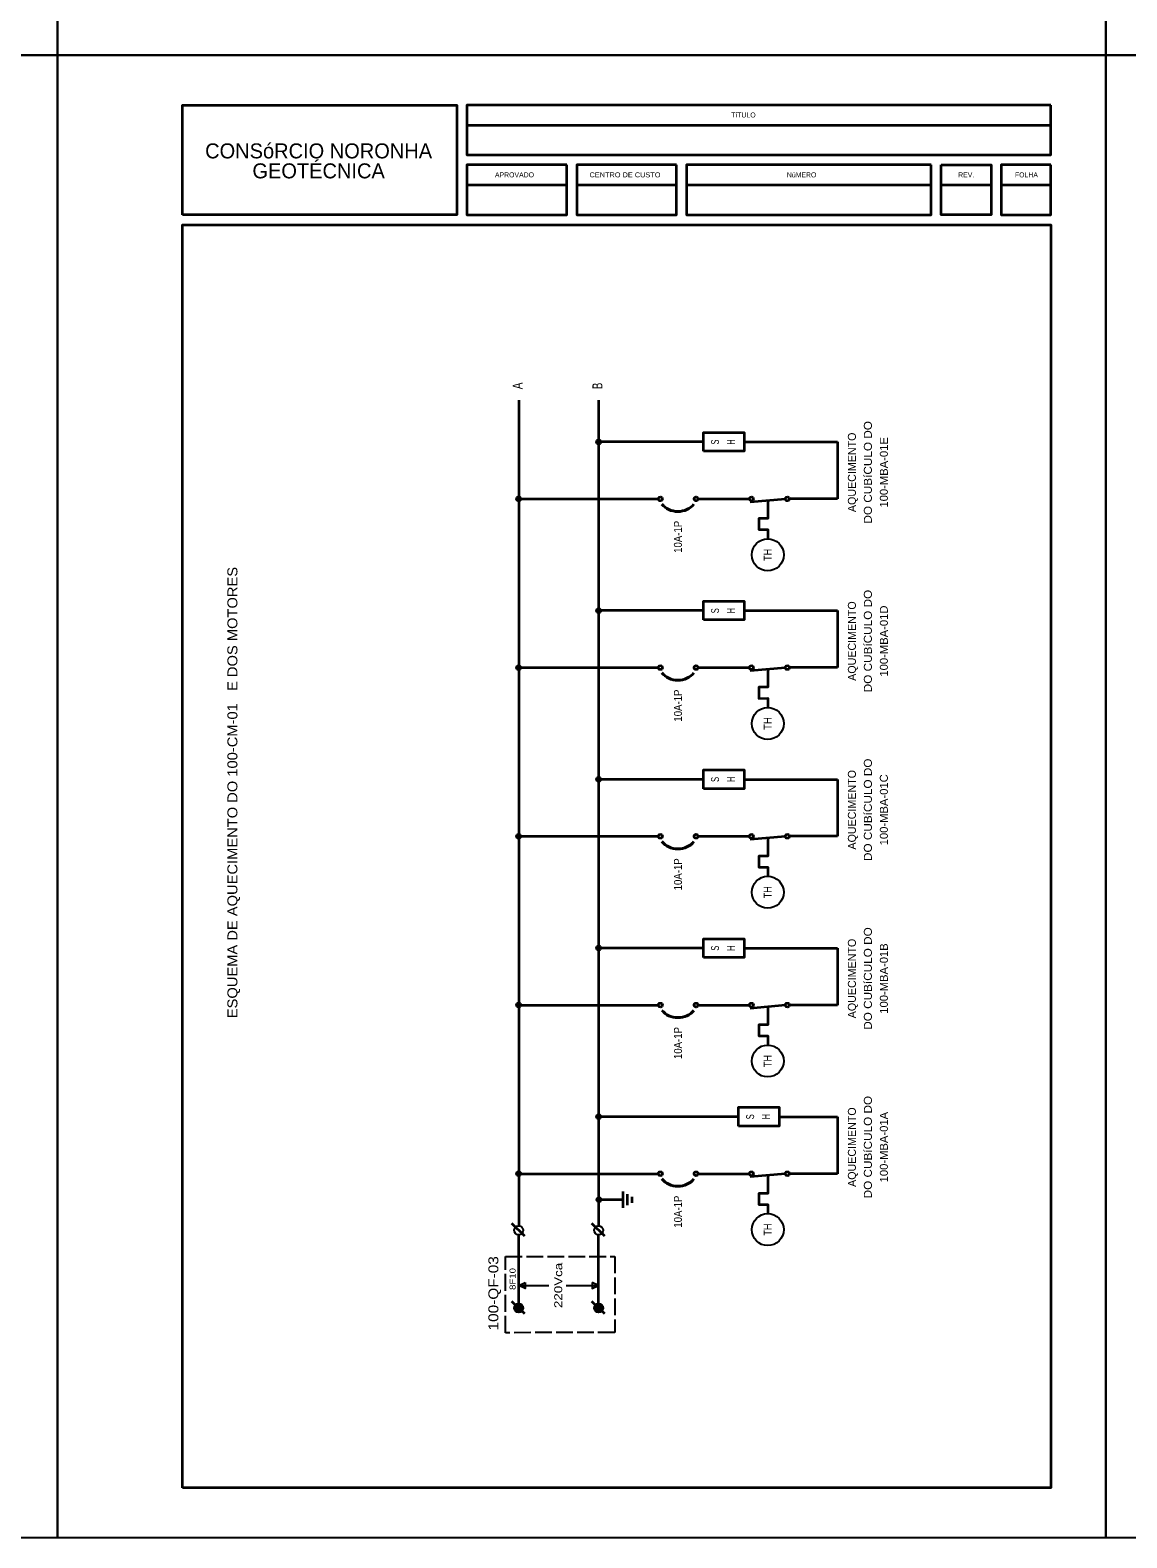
# Model space of a CAD drawing. Extents: x -4160 to -2690, y -474 to 714.
# Drawn here: x -3535.3 to -3315.6, y -473.5 to -171.5 of the extents above; entities that cross this region are included whole.
import ezdxf
from ezdxf.enums import TextEntityAlignment as Align

# ---------------------------------------------------------------- set-up
doc = ezdxf.new("R2010")
doc.units = 0
doc.header["$LTSCALE"] = 0.56
doc.linetypes.add('LONG_DASHED', pattern=[7.5, 6, -1.5])
doc.layers.add('2', color=7, linetype='Continuous', lineweight=25)
doc.layers.add('5', color=7, linetype='Continuous', lineweight=35)

msp = doc.modelspace()

# ---------------------------------------------------------------- hatches: boundary and pattern name
at = {"layer": '2'}
for points in [[(-3421.3942, -253.5808, 1), (-3421.3942, -254.4059, 1)], [(-3437.3942, -264.9938, 1), (-3437.3942, -265.819, 1)], [(-3421.3942, -287.3783, 1), (-3421.3942, -288.2035, 1)], [(-3437.3942, -298.7913, 1), (-3437.3942, -299.6165, 1)], [(-3421.3942, -321.1758, 1), (-3421.3942, -322.001, 1)], [(-3437.3942, -332.5889, 1), (-3437.3942, -333.414, 1)], [(-3421.3942, -354.9733, 1), (-3421.3942, -355.7985, 1)], [(-3437.3942, -366.3864, 1), (-3437.3942, -367.2115, 1)], [(-3421.3942, -388.7485, 1), (-3421.3942, -389.5736, 1)], [(-3437.3942, -400.1615, 1), (-3437.3942, -400.9867, 1)], [(-3421.3223, -405.3516, 1), (-3421.3223, -406.1767, 1)], [(-3437.3942, -428.3871, 1), (-3437.3942, -426.5889, 1)], [(-3421.3942, -428.3871, 1), (-3421.3942, -426.5889, 1)]]:
    msp.add_hatch(color=256, dxfattribs=at).paths.add_polyline_path(points)

# ---------------------------------------------------------------- linework, layer by layer
at = {"layer": '2', "lineweight": 35}
for p, q in [((-3437.3942, -245.6097), (-3437.3942, -411.0029)), ((-3421.3942, -245.6097), (-3421.3942, -411.0029)), ((-3400.4033, -253.9934), (-3421.3942, -253.9934)), ((-3392.219, -253.9934), (-3373.5488, -253.9934)), ((-3373.5488, -253.9934), (-3373.5488, -265.4064)), ((-3437.3942, -265.4064), (-3409.4143, -265.4064)), ((-3401.4522, -265.4064), (-3391.17, -265.4064)), ((-3383.9686, -265.4417), (-3391.0324, -266.0671)), ((-3373.5488, -265.4064), (-3383.1702, -265.4064)), ((-3400.4033, -287.7909), (-3421.3942, -287.7909)), ((-3392.219, -287.7909), (-3373.5488, -287.7909)), ((-3373.5488, -287.7909), (-3373.5488, -299.2039)), ((-3437.3942, -299.2039), (-3409.4143, -299.2039)), ((-3401.4522, -299.2039), (-3391.17, -299.2039)), ((-3383.9686, -299.2392), (-3391.0324, -299.8646)), ((-3373.5488, -299.2039), (-3383.1702, -299.2039)), ((-3400.4033, -321.5884), (-3421.3942, -321.5884)), ((-3392.219, -321.5884), (-3373.5488, -321.5884)), ((-3373.5488, -321.5884), (-3373.5488, -333.0014)), ((-3437.3942, -333.0014), (-3409.4143, -333.0014)), ((-3401.4522, -333.0014), (-3391.17, -333.0014)), ((-3383.9686, -333.0367), (-3391.0324, -333.6622)), ((-3373.5488, -333.0014), (-3383.1702, -333.0014)), ((-3400.4033, -355.3859), (-3421.3942, -355.3859)), ((-3392.219, -355.3859), (-3373.5488, -355.3859)), ((-3373.5488, -355.3859), (-3373.5488, -366.799)), ((-3437.3942, -366.799), (-3409.4143, -366.799)), ((-3401.4522, -366.799), (-3391.17, -366.799)), ((-3383.9686, -366.8342), (-3391.0324, -367.4597)), ((-3373.5488, -366.799), (-3383.1702, -366.799)), ((-3393.371, -389.161), (-3421.3942, -389.161)), ((-3385.1867, -389.161), (-3373.5488, -389.161)), ((-3373.5488, -389.161), (-3373.5488, -400.5741)), ((-3437.3942, -400.5741), (-3409.4143, -400.5741)), ((-3401.4522, -400.5741), (-3391.17, -400.5741)), ((-3383.9686, -400.6094), (-3391.0324, -401.2348)), ((-3373.5488, -400.5741), (-3383.1702, -400.5741)), ((-3416.4845, -407.4128), (-3416.4845, -404.1154)), ((-3415.6035, -406.9088), (-3415.6035, -404.6796)), ((-3421.3223, -405.7642), (-3416.4845, -405.7642)), ((-3414.6761, -406.3979), (-3414.6761, -405.1904)), ((-3438.8271, -410.5106), (-3436.2302, -413.0283)), ((-3422.8271, -410.5106), (-3420.2302, -413.0283)), ((-3437.3942, -426.5889), (-3437.3942, -412.8011)), ((-3421.3942, -426.5889), (-3421.3942, -412.8011)), ((-3438.8271, -426.0966), (-3436.2302, -428.6143)), ((-3422.8271, -426.0966), (-3420.2302, -428.6143))]:
    msp.add_line(p, q, dxfattribs=at)
at = {"layer": '2'}
for p, q in [((-3437.3942, -422.9972), (-3431.3293, -422.9972)), ((-3427.8636, -422.9972), (-3421.3942, -422.9972))]:
    msp.add_line(p, q, dxfattribs=at)
at = {"layer": '2', "lineweight": 35}
for points in [[(-3400.4032, -255.8692), (-3400.4032, -252.1176), (-3392.219, -252.1176), (-3392.219, -255.8692)], [(-3400.4032, -289.6667), (-3400.4032, -285.9151), (-3392.219, -285.9151), (-3392.219, -289.6667)], [(-3400.4032, -323.4642), (-3400.4032, -319.7126), (-3392.219, -319.7126), (-3392.219, -323.4642)], [(-3400.4032, -357.2618), (-3400.4032, -353.5102), (-3392.219, -353.5102), (-3392.219, -357.2618)], [(-3393.3709, -391.0369), (-3393.3709, -387.2853), (-3385.1867, -387.2853), (-3385.1867, -391.0369)]]:
    msp.add_lwpolyline(points, close=True, dxfattribs=at)
for points in [[(-3387.5005, -265.7544), (-3387.5005, -269.3482), (-3389.3112, -269.3482), (-3389.3112, -271.5726), (-3387.5005, -271.5612), (-3387.5005, -273.4161)], [(-3387.5005, -299.5519), (-3387.5005, -303.1457), (-3389.3112, -303.1457), (-3389.3112, -305.3702), (-3387.5005, -305.3587), (-3387.5005, -307.2136)], [(-3387.5005, -333.3494), (-3387.5005, -336.9432), (-3389.3112, -336.9432), (-3389.3112, -339.1677), (-3387.5005, -339.1562), (-3387.5005, -341.0111)], [(-3387.5005, -367.147), (-3387.5005, -370.7407), (-3389.3112, -370.7407), (-3389.3112, -372.9652), (-3387.5005, -372.9538), (-3387.5005, -374.8086)], [(-3387.5005, -400.9221), (-3387.5005, -404.5158), (-3389.3112, -404.5158), (-3389.3112, -406.7403), (-3387.5005, -406.7289), (-3387.5005, -408.5838)]]:
    msp.add_lwpolyline(points, dxfattribs=at)
at = {"layer": '2', "linetype": 'LONG_DASHED'}
msp.add_lwpolyline([(-3440.0501, -432.4233), (-3440.0501, -417.1922), (-3418.1535, -417.1701), (-3418.1535, -432.4012)], close=True, dxfattribs=at)
at = {"layer": '2'}
for points in [[(-3436.1214, -422.3926), (-3436.1214, -423.6019), (-3437.3942, -422.9972)], [(-3422.667, -422.3926), (-3422.667, -423.6019), (-3421.3942, -422.9972)]]:
    msp.add_lwpolyline(points, close=True, dxfattribs=at)
at = {"layer": '2', "lineweight": 35}
for centre, radius in [((-3421.3942, -253.9934), 0.4126), ((-3437.3942, -265.4064), 0.4126), ((-3409.0143, -265.4064), 0.4), ((-3401.8522, -265.4064), 0.4), ((-3390.77, -265.4064), 0.4), ((-3383.5701, -265.4064), 0.4), ((-3421.3942, -287.7909), 0.4126), ((-3437.3942, -299.2039), 0.4126), ((-3409.0143, -299.2039), 0.4), ((-3401.8522, -299.204), 0.4), ((-3390.77, -299.2039), 0.4), ((-3383.5701, -299.2039), 0.4), ((-3421.3942, -321.5884), 0.4126), ((-3437.3942, -333.0014), 0.4126), ((-3409.0143, -333.0014), 0.4), ((-3401.8522, -333.0015), 0.4), ((-3390.77, -333.0014), 0.4), ((-3383.5701, -333.0014), 0.4), ((-3421.3942, -355.3859), 0.4126), ((-3437.3942, -366.799), 0.4126), ((-3409.0143, -366.7989), 0.4), ((-3401.8522, -366.799), 0.4), ((-3390.77, -366.7989), 0.4), ((-3383.5701, -366.7989), 0.4), ((-3421.3942, -389.161), 0.4126), ((-3437.3942, -400.5741), 0.4126), ((-3409.0143, -400.574), 0.4), ((-3401.8522, -400.5741), 0.4), ((-3390.77, -400.574), 0.4), ((-3383.5701, -400.574), 0.4), ((-3421.3223, -405.7642), 0.4126)]:
    msp.add_circle(centre, radius, dxfattribs=at)
at = {"layer": '2'}
for centre, radius in [((-3387.5005, -276.6144), 3.1984), ((-3387.5005, -310.412), 3.1984), ((-3387.5005, -344.2095), 3.1984), ((-3387.5005, -378.007), 3.1984), ((-3387.5005, -411.7821), 3.1984), ((-3437.3942, -411.902), 0.8991), ((-3421.3942, -411.902), 0.8991), ((-3437.3942, -427.488), 0.8991), ((-3421.3942, -427.488), 0.8991)]:
    msp.add_circle(centre, radius, dxfattribs=at)
at = {"layer": '2', "lineweight": 40}
for centre in [(-3405.4993, -264.6915), (-3405.4993, -298.489), (-3405.4993, -332.2865), (-3405.4993, -366.084), (-3405.4993, -399.8591)]:
    msp.add_ellipse(centre, major_axis=(-3.8115, 0), ratio=0.85, start_param=0.57974073, end_param=2.56185197, dxfattribs=at)
at = {"layer": '5', "lineweight": 25}
for p, q in [((-3529.7642, -176.52), (-3529.7642, 120.48)), ((-3529.7642, 120.48), (-3529.7642, -176.52)), ((-3529.7642, -473.52), (-3529.7642, -176.52)), ((-3529.7642, -473.5197), (-3529.7642, -176.52)), ((-3529.7642, -473.5197), (-3739.764, -473.5197)), ((-3319.7642, -473.52), (-3529.7642, -473.52))]:
    msp.add_line(p, q, dxfattribs=at)
at = {"layer": '5'}
for p, q in [((-3447.7642, -190.52), (-3330.7642, -190.52)), ((-3447.7642, -202.52), (-3427.7642, -202.52)), ((-3425.7642, -202.52), (-3405.7642, -202.52)), ((-3403.7642, -202.52), (-3354.7642, -202.52)), ((-3352.7642, -202.52), (-3342.7642, -202.52)), ((-3340.7642, -202.52), (-3330.7642, -202.52))]:
    msp.add_line(p, q, dxfattribs=at)
at = {"layer": '5', "lineweight": 25}
for points in [[(-3319.7642, -176.52), (-3529.7642, -176.52), (-3529.7642, 120.48), (-3319.7642, 120.48)], [(-3109.7642, -176.52), (-3319.7642, -176.52), (-3319.7642, 120.48), (-3109.7642, 120.48)], [(-3109.7642, -473.52), (-3319.7642, -473.52), (-3319.7642, -176.52), (-3109.7642, -176.52)]]:
    msp.add_lwpolyline(points, close=True, dxfattribs=at)
for points in [[(-3739.7642, -176.52), (-3529.7642, -176.52), (-3739.7642, -176.52)], [(-3739.764, -176.52), (-3529.7642, -176.52), (-3529.7642, -473.5197)], [(-3529.7642, -176.52), (-3319.7642, -176.52), (-3319.7642, -473.52)]]:
    msp.add_lwpolyline(points, dxfattribs=at)
at = {"layer": '5'}
for points in [[(-3504.7642, -208.52), (-3504.7642, -186.52), (-3449.7642, -186.52), (-3449.7642, -208.52)], [(-3330.7642, -186.52), (-3447.7642, -186.52), (-3447.7642, -196.52), (-3330.7642, -196.52)], [(-3427.7642, -198.52), (-3447.7642, -198.52), (-3447.7642, -208.52), (-3427.7642, -208.52)], [(-3405.7642, -198.52), (-3425.7642, -198.52), (-3425.7642, -208.52), (-3405.7642, -208.52)], [(-3354.7642, -198.52), (-3403.7642, -198.52), (-3403.7642, -208.52), (-3354.7642, -208.52)], [(-3352.7642, -198.52), (-3342.7642, -198.52), (-3342.7642, -208.52), (-3352.7642, -208.52)], [(-3330.7642, -198.52), (-3340.7642, -198.52), (-3340.7642, -208.52), (-3330.7642, -208.52)], [(-3504.7642, -463.52), (-3504.7642, -210.52), (-3330.7642, -210.52), (-3330.7642, -463.52)]]:
    msp.add_lwpolyline(points, close=True, dxfattribs=at)

# ---------------------------------------------------------------- texts
at = {"layer": '2'}
for s, height, width, p in [('A', 2, 0.75, (-3436.626, -242.7704)), ('B', 2, 0.7, (-3420.626, -242.7704)), ('DO CUBíCULO DO', 1.6, 1.1, (-3366.6447, -260.0898)), ('S', 1.6, 0.7, (-3397.2683, -254.0117)), ('H', 1.6, 0.6, (-3394.0683, -254.0117)), ('100-MBA-01E', 1.6, 1.05, (-3363.4447, -260.0898)), ('10A-1P', 1.6, 0.9, (-3404.6953, -273.0149)), ('TH', 1.6, 0.85, (-3386.7006, -276.6146)), ('ESQUEMA DE AQUECIMENTO DO 100-CM-01   E DOS MOTORES', 2, 1.1, (-3493.7471, -324.2357)), ('DO CUBíCULO DO', 1.6, 1.1, (-3366.6447, -293.8873)), ('100-MBA-01D', 1.6, 1.05, (-3363.4447, -293.8872)), ('S', 1.6, 0.7, (-3397.2683, -287.8093)), ('H', 1.6, 0.6, (-3394.0683, -287.8092)), ('10A-1P', 1.6, 0.9, (-3404.6953, -306.8124)), ('TH', 1.6, 0.9, (-3386.7006, -310.412)), ('DO CUBíCULO DO', 1.6, 1.1, (-3366.6447, -327.6848)), ('S', 1.6, 0.7, (-3397.2683, -321.6056)), ('H', 1.6, 0.6, (-3394.0683, -321.6073)), ('100-MBA-01C', 1.6, 1.05, (-3363.4447, -327.6847)), ('10A-1P', 1.6, 0.9, (-3404.6953, -340.6099)), ('TH', 1.6, 0.85, (-3386.7006, -344.2096)), ('DO CUBíCULO DO', 1.6, 1.1, (-3366.6447, -361.4823)), ('S', 1.6, 0.7, (-3397.2683, -355.4043)), ('H', 1.6, 0.6, (-3394.0683, -355.4043)), ('100-MBA-01B', 1.6, 1.05, (-3363.4447, -361.4823)), ('10A-1P', 1.6, 0.9, (-3404.6953, -374.4074)), ('TH', 1.6, 0.85, (-3386.7006, -378.007)), ('DO CUBíCULO DO', 1.6, 1.1, (-3366.6447, -395.2575)), ('S', 1.6, 0.7, (-3390.236, -389.1783)), ('H', 1.6, 0.6, (-3387.036, -389.18)), ('100-MBA-01A', 1.6, 1.05, (-3363.4447, -395.2576)), ('10A-1P', 1.6, 0.9, (-3404.6953, -408.1825)), ('TH', 1.6, 0.85, (-3386.7006, -411.7822)), ('100-QF-03', 2, 1.15, (-3441.4674, -424.5374)), ('8F10', 1.2, 1.2, (-3438.0275, -421.6705)), ('220Vca', 1.6, 1.25, (-3428.6749, -422.9588))]:
    msp.add_text(s, height=height, rotation=90, dxfattribs=dict(at, width=width)).set_placement(p, align=Align.CENTER)
for p in [(-3369.8447, -260.0897), (-3369.8447, -293.8872), (-3369.8447, -327.6847), (-3369.8447, -361.4823), (-3369.8447, -395.2574)]:
    msp.add_text('AQUECIMENTO', height=1.6, rotation=90, dxfattribs=at).set_placement(p, align=Align.CENTER)
at = {"layer": '5'}
for s, height, p in [('TíTULO', 1, (-3392.3847, -189.009)), ('CONSóRCIO NORONHA', 3, (-3477.4749, -197.2039)), ('GEOTÉCNICA', 3, (-3477.475, -201.2039)), ('APROVADO', 1, (-3438.2387, -201.0027)), ('REV.', 1, (-3347.7443, -201.0077)), ('FOLHA', 1, (-3335.6809, -201.0077))]:
    msp.add_text(s, height=height, dxfattribs=at).set_placement(p, align=Align.CENTER)
for s, width, p in [('CENTRO DE CUSTO', 1.1, (-3416.0934, -201.0027)), ('NúMERO', 0.95, (-3380.7228, -201.0077))]:
    msp.add_text(s, height=1, dxfattribs=dict(at, width=width)).set_placement(p, align=Align.CENTER)

doc.saveas('drawing.dxf')
